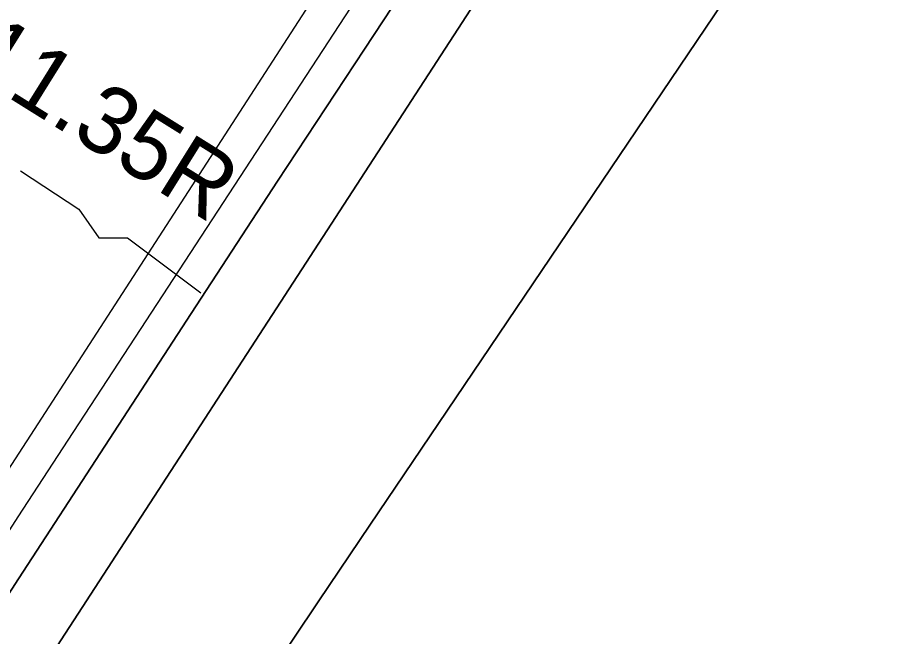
# Model space of a CAD drawing. Extents: x 3905714 to 3926767, y 183354 to 205755.
# Drawn here: x 3914998 to 3915542, y 191522 to 191907 of the extents above; entities that cross this region are included whole.
import ezdxf

# ---------------------------------------------------------------- set-up
doc = ezdxf.new("R2010")
doc.units = 0
for name, color, linetype in [('V-LEVE-TOET', 7, 'Continuous'), ('V-STRM-FMON', 7, 'Continuous'), ('V-TOPO-DPTH', 7, 'Continuous'), ('V-TOPO-MINR', 7, 'Continuous')]:
    doc.layers.add(name, color=color, linetype=linetype)

msp = doc.modelspace()

# ---------------------------------------------------------------- linework, layer by layer
at = {"layer": 'V-LEVE-TOET'}
msp.add_lwpolyline([(3914999.46, 191811.4), (3915035.71, 191787.45), (3915048.1, 191769.56), (3915065.86, 191769.73), (3915111.43, 191735.52)], dxfattribs=at)
at = {"layer": 'V-TOPO-DPTH'}
for points in [[(3915684.62, 192696.72), (3915328.37, 192146.33), (3915321.82, 192136.2), (3915315.28, 192126.07), (3915308.74, 192115.92), (3915302.21, 192105.78), (3915291.83, 192089.64), (3915290.5, 192087.56), (3915287.82, 192083.41), (3915286.48, 192081.34), (3914909.08, 191498.19)], [(3914918.97, 191435.19), (3914998.19, 191557.59), (3915051.74, 191640.11), (3915105.41, 191722.55), (3915159.27, 191804.87), (3915213.25, 191887.1), (3915300.19, 192019.21), (3915313.79, 192039.84), (3915327.42, 192060.45), (3915341.08, 192081.04), (3915354.77, 192101.61), (3915594.9, 192461.92)], [(3915594.9, 192461.92), (3915354.77, 192101.61), (3915341.08, 192081.04), (3915327.42, 192060.45), (3915313.79, 192039.84), (3915300.19, 192019.21), (3915213.25, 191887.1), (3915159.27, 191804.87), (3915105.41, 191722.55), (3915051.74, 191640.11), (3914998.19, 191557.59), (3914918.97, 191435.19)], [(3915717.58, 192352.1), (3915495.1, 192005.58), (3915481.82, 191985.04), (3915468.43, 191964.57), (3915454.91, 191944.18), (3915441.3, 191923.86), (3915216.56, 191590.83), (3915184.9, 191543.76), (3915153.33, 191496.63)], [(3915153.33, 191496.63), (3915184.9, 191543.76), (3915216.56, 191590.83), (3915441.3, 191923.86), (3915454.91, 191944.18), (3915468.43, 191964.57), (3915481.82, 191985.04), (3915495.1, 192005.58), (3915717.58, 192352.1)], [(3914929.82, 191373.85), (3915305.59, 191952.33), (3915314.91, 191966.64), (3915324.26, 191980.92), (3915333.64, 191995.18), (3915343.04, 192009.43), (3915357.4, 192031.1), (3915359.66, 192034.48), (3915361.95, 192037.86), (3915364.26, 192041.21), (3915366.58, 192044.54), (3915398.28, 192089.56), (3915416.62, 192115.29), (3915435.16, 192140.87), (3915454, 192166.22), (3915473.04, 192191.43), (3915530.12, 192266.08), (3915577.2, 192328.96)], [(3914929.82, 191373.85), (3915305.59, 191952.33), (3915314.91, 191966.64), (3915324.26, 191980.92), (3915333.64, 191995.18), (3915343.04, 192009.43), (3915357.4, 192031.1), (3915359.66, 192034.48), (3915361.95, 192037.86), (3915364.26, 192041.21), (3915366.58, 192044.54), (3915398.28, 192089.56), (3915416.62, 192115.29), (3915435.16, 192140.87), (3915454, 192166.22), (3915473.04, 192191.43), (3915530.12, 192266.08), (3915577.2, 192328.96)]]:
    msp.add_lwpolyline(points, dxfattribs=at)
at = {"layer": 'V-TOPO-MINR'}
for points in [[(3915684.62, 192696.72), (3915328.37, 192146.33), (3915321.82, 192136.2), (3915315.28, 192126.07), (3915308.74, 192115.92), (3915302.21, 192105.78), (3915291.83, 192089.64), (3915290.5, 192087.56), (3915287.82, 192083.41), (3915286.48, 192081.34), (3914909.08, 191498.19)], [(3915594.9, 192461.92), (3915354.77, 192101.61), (3915341.08, 192081.04), (3915327.42, 192060.45), (3915313.79, 192039.84), (3915300.19, 192019.21), (3915213.25, 191887.1), (3915159.27, 191804.87), (3915105.41, 191722.55), (3915051.74, 191640.11), (3914998.19, 191557.59), (3914918.97, 191435.19)], [(3915558.62, 192453.25), (3915516.92, 192389.85), (3915475.25, 192326.44), (3915433.62, 192263), (3915392.02, 192199.54), (3915348.06, 192132.41), (3915328.47, 192102.5), (3915308.89, 192072.58), (3915289.32, 192042.65), (3915269.76, 192012.72), (3915060.01, 191691.6), (3915028.85, 191643.82), (3914997.75, 191596.02), (3914966.71, 191548.17), (3914935.73, 191500.29)], [(3915717.58, 192352.1), (3915495.1, 192005.58), (3915481.82, 191985.04), (3915468.43, 191964.57), (3915454.91, 191944.18), (3915441.3, 191923.86), (3915216.56, 191590.83), (3915184.9, 191543.76), (3915153.33, 191496.63)], [(3915577.2, 192328.96), (3915530.12, 192266.08), (3915473.04, 192191.43), (3915454, 192166.22), (3915435.16, 192140.87), (3915416.62, 192115.29), (3915398.28, 192089.56), (3915366.58, 192044.54), (3915364.26, 192041.21), (3915361.95, 192037.86), (3915359.66, 192034.48), (3915357.4, 192031.1), (3915343.04, 192009.43), (3915333.64, 191995.18), (3915324.26, 191980.92), (3915314.91, 191966.64), (3915305.59, 191952.33), (3914929.82, 191373.85)]]:
    msp.add_lwpolyline(points, dxfattribs=at)

# ---------------------------------------------------------------- texts
at = {"layer": 'V-STRM-FMON'}
msp.add_text('11.35R', height=42, rotation=328.0157, dxfattribs=at).set_placement((3914963.51, 191874.56))

doc.saveas('drawing.dxf')
